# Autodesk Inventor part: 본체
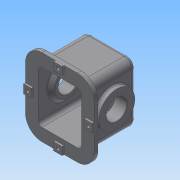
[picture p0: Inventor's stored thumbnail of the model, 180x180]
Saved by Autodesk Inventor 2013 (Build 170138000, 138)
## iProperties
Created: 2014-11
Part Number: 본체
Material: 일반
Document SubType Name: Modeling
Designer: Administrator
Density: 1 g/cm^3
Author: Administrator
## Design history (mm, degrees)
sketch "스케치1"
  geometry: L1 (-65, 64)-(65, 64); L2 (65, 64)-(65, -64); L3 (65, -64)-(-65, -64); L4 (-65, -64)-(-65, 64); L5 (-65, 64)-(65, -64); L6 (65, 64)-(-65, -64); 1 further point
  constraints: 12 end point, 2 midpoint, 2 parallel, 1 horizontal, 1 perpendicular
  dimensions: "d0" = 130 distance of L2.end L3.end; "d1" = 128 distance of L1.end L2.end
extrude "돌출1" new body sketch "스케치1" stored distance "d2" = 152; taper "d3" = 0 deg
sketch "스케치2"
  geometry: L1 (130, 0)-(130, -152) reference; L2 (0, 0)-(130, 0) reference; L3 (0, 0)-(0, -152) reference; L4 (130, -152)-(0, -152) reference; L5 (-22, 22)-(152, 22); L6 (152, 22)-(152, -174); L7 (152, -174)-(-22, -174); L8 (-22, -174)-(-22, 22); L9 (-22, 22)-(152, -174); L10 (152, 22)-(-22, -174); 1 further point
  constraints: 12 end point, 2 midpoint, 2 parallel, 1 horizontal, 1 perpendicular
  dimensions: "d4" = 174 distance of L6.end L7.end; "d6" = 196 distance of L5.end L6.end
extrude "돌출2" join sketch "스케치2" distance "d7" = 10; taper "d8" = 0 deg
fillet "모깎기1" dims "d27" = 10
fillet "모깎기2" dims "d28" = 20
fillet "모깎기3" dims "d29" = 42
feature "쉘1" dims "d30" = 10
sketch "스케치7"
  geometry: L1 (0, -10)-(112, -10) reference; C1 r 45.5 at (56, 58); 1 further point
  constraints: 1 centre point, 1 coincident
  dimensions: "d42" = 91 diameter of C1; "d126" = 68 distance from line of L1 point (56, 58)
extrude "돌출5" join sketch "스케치7" distance "d43" = 12; taper "d44" = 0 deg
sketch "스케치8"
  geometry: C1 r 45.5 at (0, 0) reference; C2 r 26 at (0, 0)
  constraints: 1 centre point, 1 coincident
  dimensions: "d45" = 52 diameter of C2
extrude "돌출6" cut sketch "스케치8" distance "d46" = 32; taper "d47" = 0 deg
sketch "스케치9" dims "d48" = 70
  geometry: C1 r 45.5 at (0, 0) reference; 2 further points
  constraints: 2 vertical alignment, 1 coincident, 2 other
hole "구멍3" sketch "스케치9" at (0, 35) diameter "d49" = 3.242; stored, may be unused: countersink angle "d53" = 90 deg, drill point angle "d55" = 118 deg; dims "d50" = 13, "d51" = 4, "d52" = 2, "d54" = 16
sketch "스케치10"
  geometry: L1 (45, 54)-(55, 54) reference; L2 (55, -64)-(55, 54) reference; L3 (45, -64)-(55, -64) reference; L4 (45, 54)-(45, -64) reference; L5 (77, -41.5)-(65, -41.5) reference; L6 (65, -41.5)-(65, -54) reference; L7 (65, -54)-(87, -54) reference; L8 (87, -54)-(87, -64) reference; L9 (87, -64)-(55, -64) reference; L10 (55, -64)-(55, -22) reference; L11 (55, -22)-(77, -22) reference; L12 (77, -22)-(77, -29.379) reference; L13 (77, -29.379)-(61, -29.379) reference; L14 (61, -29.379)-(60.026, -31) reference; L15 (60.026, -31)-(61, -32.621) reference; L16 (61, -32.621)-(77, -32.621) reference; L17 (77, -32.621)-(77, -41.5) reference; L18 (65, 54)-(65, 49.5) reference; L19 (65, 49.5)-(77, 49.5) reference; L20 (77, 49.5)-(77, 40.621) reference; L21 (77, 40.621)-(61, 40.621) reference; L22 (61, 40.621)-(60.026, 39) reference; L23 (60.026, 39)-(61, 37.379) reference; L24 (61, 37.379)-(77, 37.379) reference; L25 (77, 37.379)-(77, 30) reference; L26 (77, 30)-(55, 30) reference; L27 (55, 30)-(55, 54) reference; L28 (55, 54)-(-55, 54) reference; L29 (-55, 54)-(-55, -64) reference; L30 (-55, -64)-(-87, -64) reference; L31 (-87, -64)-(-87, -54) reference; L32 (-87, -54)-(-65, -54) reference; L33 (-65, -54)-(-65, 54) reference; L34 (-55, 64)-(55, 64) reference; L35 (45, 39.5)-(45, 4); L36 (77, 30)-(77, -22) reference; L37 (45, 4)-(55, 4); L38 (45, 39.5)-(55, 49.5); A1 r 10 centre (55, 54) between (65, 54) and (55, 64) reference; A2 r 10 centre (-55, 54) between (-55, 64) and (-65, 54) reference; 2 further points
  constraints: 6 end point, 2 point on line, 1 horizontal alignment, 1 midpoint, 1 parallel, 1 perpendicular
  dimensions: "d127" = 10 distance of L35.end L37.end; "d130" = 91 diameter of L38.end L37; "d131" = 71 diameter of L35.start L37
  node "투영된 루프1"
  node "절단 모서리 투영1"
node "작업 평면1"
chamfer "모따기1" distance "d69" = 1; stored, may be unused: second distance "d70" = 2, angle "d71" = 45 deg
fillet "모깎기4" dims "d72" = 3
fillet "모깎기5" dims "d79" = 3
node "작업 평면2"
node "작업 평면3"
sketch "스케치16"
  geometry: L1 (-22, 132)-(-22, 20) reference; C1 r 7 at (-12, 76); 3 further points
  constraints: 1 centre point, 1 coincident, 1 horizontal alignment, 1 midpoint
  dimensions: "d95" = 14 diameter of C1; "d96" = 10 distance from line of C1.centre L1
hole "구멍4" sketch "스케치16" at (-12, 76) diameter "d97" = 9; stored, may be unused: countersink angle "d101" = 90 deg, drill point angle "d103" = 0 deg; dims "d98" = 50, "d99" = 14, "d100" = 8.6, "d102" = 20
sketch "스케치17"
  geometry: L1 (20, -22)-(110, -22) reference; 3 further points
  constraints: 1 midpoint, 1 vertical alignment
  dimensions: "d104" = 10 distance from line of L1 point (65, -12)
hole "구멍5" sketch "스케치17" at (65, -12) diameter "d105" = 9; stored, may be unused: countersink angle "d109" = 90 deg, drill point angle "d111" = 0 deg; dims "d106" = 50, "d107" = 14, "d108" = 8.6, "d110" = 20
sketch "스케치18"
  geometry: L1 (112, 87)-(132, 87); L2 (132, 87)-(132, 109); L3 (132, 109)-(112, 109); L4 (112, 109)-(112, 87); L5 (112, 87)-(132, 109); L6 (132, 87)-(112, 109); C1 r 4.5 at (122, 98) reference; 1 further point
  constraints: 12 end point, 2 midpoint, 2 parallel, 1 horizontal, 1 perpendicular
  dimensions: "d112" = 20 distance of L3.end L2.end; "d113" = 22 distance of L1.end L2.end
extrude "돌출12" join sketch "스케치18" distance "d114" = 5; taper "d115" = 0 deg
sketch "스케치19"
  geometry: L1 (34, 20)-(56, 20); L2 (56, 20)-(56, 0); L3 (56, 0)-(34, 0); L4 (34, 0)-(34, 20); L5 (34, 20)-(56, 0); L6 (56, 20)-(34, 0); C1 r 4.5 at (45, 10) reference; 1 further point
  constraints: 12 end point, 2 midpoint, 2 parallel, 1 horizontal, 1 perpendicular
  dimensions: "d116" = 22 distance of L2.end L3.end; "d117" = 20 distance of L1.end L2.end
extrude "돌출13" join sketch "스케치19" distance "d118" = 5; taper "d119" = 0 deg
fillet "모깎기8" dims "d120" = 3
fillet "모깎기10" dims "d122" = 3
sketch "스케치20"
  geometry: L1 (-45, -64)-(-11, -64) reference; 2 further points
  constraints: 1 vertical alignment, 1 other
  dimensions: "d123" = 92 distance from line of L1 point (0, 28)
feature "엠보싱1" sketch "스케치20" dims "d6" = 196, "d124" = 1, "d125" = 0
revolve "회전2" stored, may be unused: angle "d132" = 90 deg
sketch "스케치21"
  geometry: C1 r 35.5 at (0, 0) reference; C2 r 26 at (0, 0); 1 further point
  constraints: 1 centre point, 1 coincident
  dimensions: "d133" = 52 diameter of C2
extrude "돌출14" cut sketch "스케치21" stored distance "d134" = 10; taper "d135" = 0 deg
sketch "스케치22"
  geometry: C1 r 35.5 at (0, 0) reference; C2 r 26 at (0, 0); 1 further point
  constraints: 1 centre point, 1 concentric
  dimensions: "d136" = 52 diameter of C2
extrude "돌출15" cut sketch "스케치22" stored distance "d137" = 10; taper "d138" = 0 deg
sketch "스케치23"
  geometry: L1 (64, 18.939)-(94.566, 12.442); L2 (94.566, 12.442)-(81.675, -48.203); L3 (81.675, -48.203)-(64, -44.446); L4 (-62.6, -92.5)-(-62.6, -95) reference; L5 (-62.6, -95)-(-54, -95) reference; L6 (-54, -95)-(-54, -98) reference; L7 (-54, -98)-(-69, -98) reference; L8 (-69, -98)-(-69, -92.5) reference; L9 (-69, -92.5)-(-62.6, -92.5) reference; L10 (-62.6, 95)-(-62.6, 92.5) reference; L11 (-62.6, 92.5)-(-69, 92.5) reference; L12 (-69, 92.5)-(-69, 98) reference; L13 (-69, 98)-(-54, 98) reference; L14 (-54, 98)-(-54, 95) reference; L15 (-54, 95)-(-62.6, 95) reference; L16 (64, 66)-(64, -66) reference; L17 (54, -76)-(-51, -76) reference; L18 (-54, -79)-(-54, -81) reference; L19 (-54, -81)-(-62.6, -81) reference; L20 (-62.6, -81)-(-62.6, -83.5) reference; L21 (-62.6, -83.5)-(-69, -83.5) reference; L22 (-69, -83.5)-(-69, -78) reference; L23 (-69, -78)-(-64, -78) reference; L24 (-64, -78)-(-64, -66) reference; L25 (-64, -66)-(51, -66) reference; L26 (54, -63)-(54, 63) reference; L27 (51, 66)-(-64, 66) reference; L28 (-64, 66)-(-64, 78) reference; L29 (-64, 78)-(-69, 78) reference; L30 (-69, 78)-(-69, 83.5) reference; L31 (-69, 83.5)-(-62.6, 83.5) reference; L32 (-62.6, 83.5)-(-62.6, 81) reference; L33 (-62.6, 81)-(-54, 81) reference; L34 (-54, 81)-(-54, 79) reference; L35 (-51, 76)-(31.153, 76) reference; L36 (31.153, 76)-(31.153, 77) reference; L37 (31.153, 77)-(31.815, 77) reference; L38 (31.815, 77)-(31.815, 76) reference; L39 (31.815, 76)-(54, 76) reference; L40 (4, 0)-(88.121, -17.88); L41 (-62.6, -92.5)-(-62.6, -95) reference; L42 (-62.6, -95)-(-54, -95) reference; L43 (-54, -95)-(-54, -98) reference; L44 (-54, -98)-(-69, -98) reference; L45 (-69, -98)-(-69, -92.5) reference; L46 (-69, -92.5)-(-62.6, -92.5) reference; L47 (-62.6, 95)-(-62.6, 92.5) reference; L48 (-62.6, 92.5)-(-69, 92.5) reference; L49 (-69, 92.5)-(-69, 98) reference; L50 (-69, 98)-(-54, 98) reference; L51 (-54, 98)-(-54, 95) reference; L52 (-54, 95)-(-62.6, 95) reference; L53 (64, 66)-(64, -66) reference; L54 (54, -76)-(-51, -76) reference; L55 (-54, -79)-(-54, -81) reference; L56 (-54, -81)-(-62.6, -81) reference; L57 (-62.6, -81)-(-62.6, -83.5) reference; L58 (-62.6, -83.5)-(-69, -83.5) reference; L59 (-69, -83.5)-(-69, -78) reference; L60 (-69, -78)-(-64, -78) reference; L61 (-64, -78)-(-64, -66) reference; L62 (-64, -66)-(51, -66) reference; L63 (54, -63)-(54, 63) reference; L64 (51, 66)-(-64, 66) reference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; C1 r 26 at (4, 0) reference; A1 r 10 centre (54, -66) between (54, -76) and (64, -66) reference; A2 r 3 centre (-51, -79) between (-51, -76) and (-54, -79) reference; A3 r 3 centre (51, -63) between (51, -66) and (54, -63) reference; A4 r 3 centre (51, 63) between (54, 63) and (51, 66) reference; A5 r 3 centre (-51, 79) between (-54, 79) and (-51, 76) reference; A6 r 10 centre (54, 66) between (64, 66) and (54, 76) reference; A7 r 10 centre (54, -66) between (54, -76) and (64, -66) reference; A8 r 3 centre (-51, -79) between (-51, -76) and (-54, -79) reference; A9 r 3 centre (51, -63) between (51, -66) and (54, -63) reference; A10 r 3 centre (51, 63) between (54, 63) and (51, 66) reference; A11 r 3 centre (-51, 79) between (-54, 79) and (-51, 76) reference; A12 r 10 centre (54, 66) between (64, 66) and (54, 76) reference
  constraints: 8 end point, 2 parallel, 2 point on line, 1 coincident, 1 midpoint, 1 perpendicular
  dimensions: "d139" = 12 deg angle of L27 L40; "d140" = 62 distance of L1.end L2.end; "d142" = 86 distance from line of L40.start L2
extrude "돌출16" join sketch "스케치23" stored distance "d143" = 62; taper "d144" = 0 deg
fillet "모깎기11" dims "d145" = 31
sketch "스케치24"
  geometry: C1 r 31 at (0, 0) reference; 1 further point
  constraints: 1 coincident
hole "구멍6" sketch "스케치24" at (0, 0) diameter "d146" = 30; stored, may be unused: countersink angle "d150" = 90 deg, drill point angle "d152" = 118 deg; dims "d147" = 6, "d148" = 42, "d149" = 25, "d151" = 50
fillet "모깎기12" dims "d153" = 3
fillet "모깎기13" dims "d154" = 0.3
fillet "모깎기14" dims "d155" = 3
chamfer "모따기3" distance "d156" = 1; stored, may be unused: second distance "d157" = 2, angle "d158" = 45 deg
node "솔리드1"
pattern_circular "원형 패턴3" dims angle "d57" = 360 deg
mirror "대칭3"
mirror "대칭4"
mirror "대칭5"
mirror "대칭6"
mirror "대칭7"
mirror "대칭8"
mirror "대칭9"
node "절단 모서리 투영3"
node "절단 모서리 투영4"
